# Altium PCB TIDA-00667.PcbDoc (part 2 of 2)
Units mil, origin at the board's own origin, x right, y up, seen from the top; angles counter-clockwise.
Board outline 4000 x 4000 mil, 6 copper layers (Top, Inner Layer 2, Inner Layer 3, Inner Layer 4, Inner Layer 5, Bottom), stack 58.1 mil thick; 114 components, 88 nets, 384 pads, 631 vias.
Unrouted connection lines stored in the file: 538.
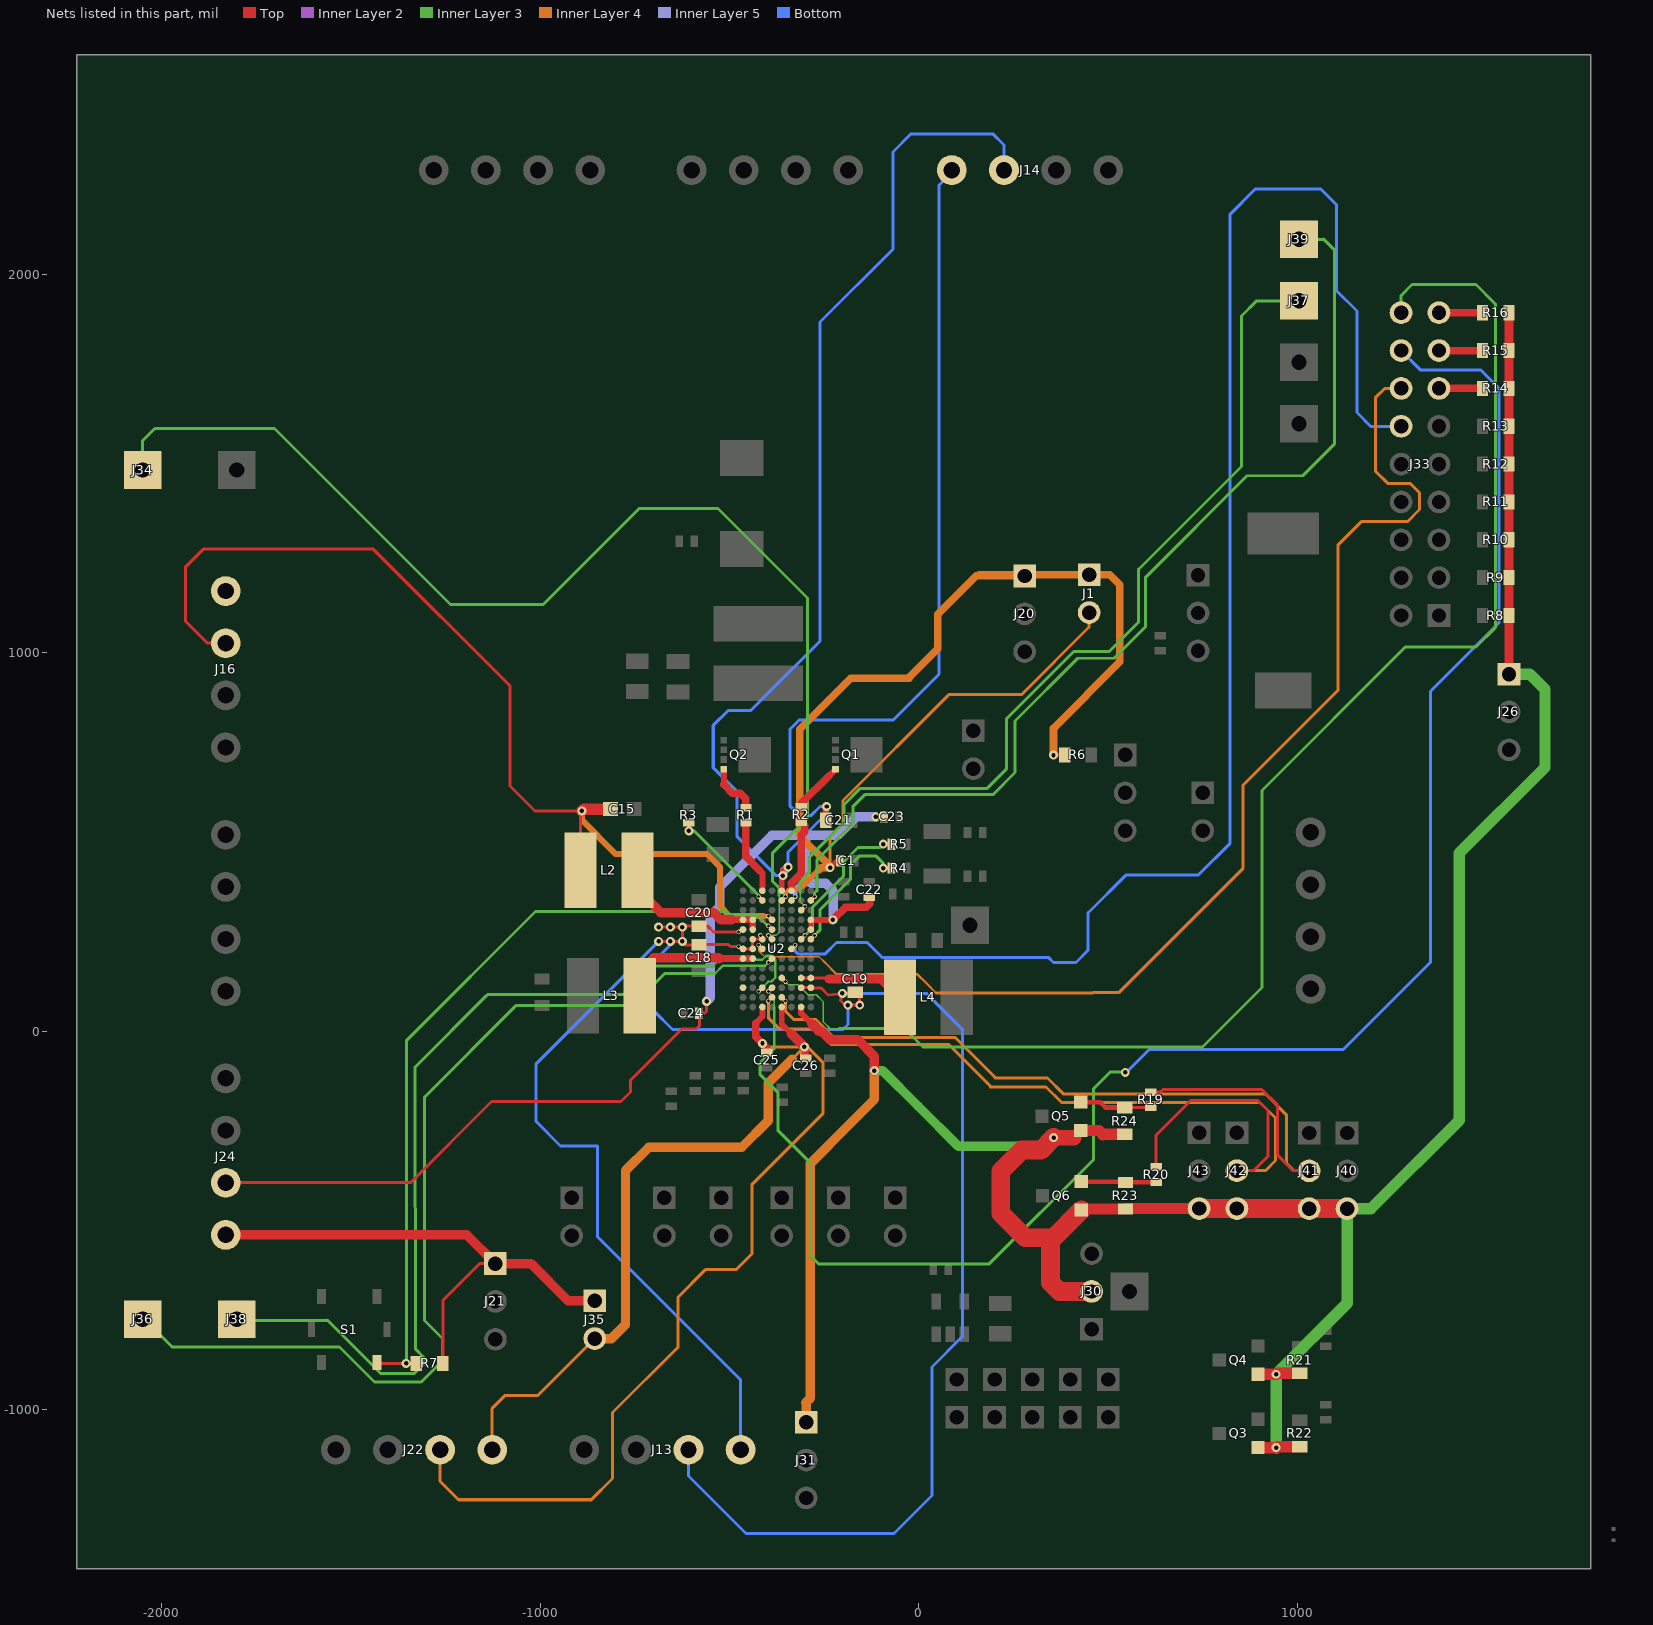
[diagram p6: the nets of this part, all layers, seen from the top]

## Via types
v1: diameter 23.62/23.62/23.62/23.62/23.62/23.62 (per signal layer), hole 11.81, Top to Bottom, 568 vias
v2: diameter 11.81/11.81/11.81/11.81/11.81/11.81 (per signal layer), hole 7.87, Top to Bottom, 63 vias

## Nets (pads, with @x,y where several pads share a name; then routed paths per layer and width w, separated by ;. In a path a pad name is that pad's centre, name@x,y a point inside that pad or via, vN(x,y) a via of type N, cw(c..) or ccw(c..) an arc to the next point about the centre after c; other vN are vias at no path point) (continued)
NetJ33_12: J33.12 U2.G6 | length 4095.4
  Top w9.84: U2.G6@-336.61,217.5 v2(-326.72,227.39)
  Bottom w7.87: v2(-326.72,227.39) -326.72,211.39 -319.91,204.58 -247.12,204.58 -217.42,234.28 -136.48,234.28 -97.47,195.27 342.14,195.27 355.67,181.74 415.01,181.74 447,213.73 447,313.4 448.37,313.4 548.14,413.17 738.65,413.17 822.35,496.87 822.35,2158.68 888.3,2224.63 1062.47,2224.63 1103.59,2183.51 1103.59,1956.1 1157.23,1902.46 1157.23,1634.4 1193.43,1598.2 1273.9,1598.2 J33.12@1274,1598.3
NetJ33_13: J33.13 R14.2 | length 115
  Top w19.68: J33.13@1374,1698.3 R14.2@1489,1698.3
NetJ33_14: J33.14 U2.G3 | length 3160.3
  Top w9.84: v2(-423.28,227.39) U2.G3@-413.39,217.5
  Inner Layer 4 w4: v2(-423.28,227.39) -423.28,212.87 -407.63,197.22 -263.6,197.22 -248.92,182.54 -248.92,182.29
  Inner Layer 4 w6: -248.92,182.29 -218.12,151.49 -4.67,151.49 21.92,124.9 44.7,101.51
  Inner Layer 4 w7.87: 44.7,101.51 459.73,101.51 460.07,101.85 527.93,101.85 856.8,430.72 856.8,650.52 1107.76,901.48 1107.76,1285.25 1168.74,1346.23 1290.94,1346.23 1322.75,1378.04 1322.75,1422.42 1297.77,1447.4 1238.65,1447.4 1205.73,1480.32 1205.73,1673.3 1230.73,1698.3 J33.14@1274,1698.3
NetJ33_15: J33.15 R15.2 | length 115
  Top w20: J33.15@1374,1798.3 R15.2@1489,1798.3
NetJ33_16: J33.16 U2.L4 | length 4771.2
  Top w9.84: v2(-397.69,105.25) U2.L4@-387.8,115.14
  Inner Layer 3 w4: v2(-397.69,105.25) -382.06,89.62 -382.06,61.83
  Inner Layer 3 w7.87: -382.06,61.83 -382.06,-45.75 -420.29,-83.98 -420.29,-113.45 -372.73,-161.01 -372.73,-263.9 -370.42,-263.9 -285.82,-348.5 -285.82,-593.99 -265.38,-614.43 185.95,-614.43 461.81,-338.57 461.81,-151.44 504.95,-108.3 544.99,-108.3 v1(545.18,-108.48)
  Bottom w7.87: v1(545.18,-108.48) 548.38,-108.48 609.15,-47.71 1121.88,-47.71 1351.68,182.09 1351.68,864.22 1351.68,897.91 1532.94,1079.17 1532.94,1698.63 1484.66,1746.91 1323.51,1746.91 1323.51,1748.79 J33.16@1274,1798.3
NetJ33_17: J33.17 R16.2 | length 115
  Top w19.68: J33.17@1374,1898.3 R16.2@1489,1898.3
NetJ33_18: J33.18 U2.K5 | length 3939.4
  Top w9.84: U2.K5@-362.2,140.73 v2(-352.31,130.84)
  Inner Layer 3 w4: v2(-352.31,130.84) -343.67,122.24 -318.63,122.24 -292.83,96.44 -271.19,96.44 -252.3,77.55 -252.3,24.3 -234.34,6.34 -211.31,6.34 -210.86,6.79
  Inner Layer 3 w7.87: -210.86,6.79 -37.61,6.79 10.85,-41.67 749.29,-41.67 906.36,115.4 906.36,636.19 1285.25,1015.08 1471.98,1015.08 1523,1066.1 1523,1921.48 1471.92,1972.56 1303.09,1972.56 1273.57,1943.04 1274,1942.61 J33.18@1274,1898.3
NetJ34_1: J34.1 U2.F4 | length 3218.4
  Top w9.84: v2(-397.69,252.98) U2.F4@-387.8,243.09
  Inner Layer 3 w4: v2(-397.69,252.98) -377.08,252.98 -368.98,261.08 -368.98,359.15
  Inner Layer 3 w7.87: J34.1@-2050.51,1482.46 J34.1@-2050.51,1482.46 -2050.47,1560.46 -2018.39,1592.54 -1702.27,1592.54 -1237.14,1127.41 -992.27,1127.41 -739.08,1380.6 -739.08,1380.7 -530.39,1380.7 -294.51,1144.82 -294.51,562.65 -387.22,469.94 -387.22,396.79 -368.98,378.55 -368.98,359.15
NetJ36_1: J36.1 U2.H4 | length 2670.5
  Top w9.84: v2(-397.69,182.02) U2.H4@-387.8,191.91
  Inner Layer 3 w6: -538.23,152.88 -518.75,172.36 -518.75,172.75 -405.73,172.75 -397.69,180.79 v2@-397.69,181.13
  Inner Layer 3 w7.87: J36.1@-2050.51,-761.03 -2045.6,-761.03 -1972.7,-833.93 -1530.43,-833.93 -1437.96,-926.4 -1314.72,-926.4 -1258.75,-870.43 -1258.75,-811.67 -1306.32,-764.1 -1306.32,-174.26 -1063.43,68.63 -754.79,68.63 -670.54,152.88 -538.23,152.88 ; v2@-397.69,181.13 v2(-397.69,182.02)
NetJ37_1: J37.1 U2.C7 | length 2482.7
  Top w9.84: U2.C7@-311.02,319.86 v2(-301.13,329.75)
  Inner Layer 3 w4: -313.89,369.6 -313.89,342.65 v2(-301.13,329.75)
  Inner Layer 3 w7.87: 852.59,1492 852.59,1889.84 892.34,1929.59 1003.61,1929.59 J37.1@1003.8,1929.78
  Inner Layer 3 w8: -313.89,369.6 -314.03,394.95 -289.44,419.54 -289.44,459.3 -197.28,551.46 -197.28,599.09 -154.5,641.87 180.56,641.87 231.05,692.36 231.05,824.97 409.27,1003.19 503.16,1003.19 579.79,1079.82 579.79,1221.1 581.69,1221.1 852.59,1492
NetJ38_1: J38.1 U2.L3 | length 2562.1
  Top w9.84: v2(-423.28,105.25) U2.L3@-413.39,115.14
  Inner Layer 3 w6: J38.1@-1803.6,-764.27 J38.1@-1795.72,-764.27 ; -543.24,172.83 -527.53,188.54 -527.53,188.91 -413.58,188.91 -402.95,199.54 -389.1,199.54 -379.39,189.83 -379.39,141.33 -389.1,131.62 -397.88,131.62 -397.88,130.64 v2(-423.28,105.25)
  Inner Layer 3 w8: J38.1@-1803.6,-764.27 J38.1@-1802.04,-761.03 ; J38.1@-1795.72,-764.27 -1564.87,-764.27 -1563.24,-762.64 -1422.02,-903.86 -1332.6,-903.86 -1307.62,-878.88 -1307.62,-861.86 -1330.33,-839.15 -1330.63,-94.34 -1144.1,92.19 -1139.78,96.5 -779.49,96.5 -703.16,172.83 -543.24,172.83
NetJ39_1: J39.1 U2.B8 | length 2737.5
  Top w9.84: U2.B8@-285.43,345.45 v2(-275.54,355.34)
  Inner Layer 3 w7.87: v2(-275.54,355.34) -275.54,365.3 -269.7,371.14 -269.7,452.35 -174.49,547.56 -174.49,593.27 -142.75,625.01 195.94,625.01 254.22,683.29 254.22,819.62 419.97,985.37 515.36,985.37 599.12,1069.13 599.12,1199.53 867.09,1467.5 1014.1,1467.5 1097.57,1550.97 1097.57,2064.26 1069.47,2092.36 1069.39,2092.28 J39.1@1003.8,2092.28
NetL2_1: L2.1 U2.D1 U2.D2 U2.E2 | length 499.9
  Top w3.94: U2.E2@-438.98,268.68 U2.E2@-438.98,270.94
  Top w7.87: L2.1@-743.75,425 L2.1@-740,468.75
  Top w17: -493.75,294.27 U2.D1@-464.57,294.27 U2.D2@-438.98,294.27 U2.E2@-438.98,270.94
  Top w25: L2.1@-740,468.75 -740,371.27 -682,313.27 -542,313.27 -523,294.27 -493.75,294.27
NetL3_1: L3.1 U2.H1 U2.H2 | length 490.4
  Top w7.87: L3.1@-741.91,39.41 L3.1@-737.5,93.75 ; -700,194 -699.91,194
  Top w12: U2.H1@-464.57,191.91 -464.57,192 U2.H1@-464.57,194
  Top w18: -527,192 U2.H1@-464.57,192 ; U2.H1@-464.57,191.91 U2.H2@-438.98,191.91
  Top w25: L3.1@-741.91,39.41 -741.91,152.09 -700,194 ; -699.91,194 -529,194 -527,192
NetL4_1: L4.1 U2.K7 U2.K8 | length 287.4
  Top w7.87: U2.K7@-311.02,140.73 U2.K8@-285.43,140.73 -239.73,140.73 -238.36,139.36 ; -237,138 -238.36,139.36 ; -235,135.12 -238.36,138.48 -238.36,139.36
  Top w25: -237,138 -99,138 L4.1@-50,90
NetQ1_4: Q1.4 R2.2 | length 137.1
  Top w16: -236.87,675.37 Q1.4@-220.12,692.12
  Top w20: R2.2@-310.31,592.4 -310.31,601.93 -236.87,675.37
NetQ2_4: Q2.4 R1.2 | length 137.7
  Top w16: -515.28,651.87 Q2.4@-515.28,692.12
  Top w20: -515.28,651.87 -492.49,629.08 -472.18,629.08 -456.78,613.68 R1.2@-456.78,590.58
NetR1_1: R1.1 U2.A3 | length 198.5
  Top w10: R1.1@-457.91,549.45 R1.1@-456.78,550.58
  Top w16: -419.82,424.38 -413.39,417.95 U2.A3@-413.39,371.04
  Top w20: R1.1@-457.91,549.45 -457.91,462.35 -457.79,462.35 -419.82,424.38
NetR2_1: R2.1 U2.A6 | length 199.5
  Top w10: R2.1@-301.51,542.56 R2.1@-301.51,543.6
  Top w17: U2.A6@-336.61,371.04 -336.61,390.77
  Top w20: -336.61,390.77 -310.31,417.07 -310.31,517.92 -301.51,526.72 R2.1@-301.51,542.56 ; R2.1@-310.31,552.4 R2.1@-301.51,543.6
NetR3_1: R3.1 U2.B3 | length 294.4
  Top w7.87: v1(-607.76,529.24) R3.1@-607.76,550.58
  Top w9.84: v2(-423.28,355.34) U2.B3@-413.39,345.45
  Inner Layer 3 w7.87: v1(-607.76,529.24) -594.83,529.24 -594.25,529.82 -465.41,400.97 -423.28,358.84 v2(-423.28,355.34)
NetR4_2: R4.2 U2.F8 | length 378.3
  Top w7.87: v1(-94.09,431.13) -94.09,431.21 R4.2@-72.2,431.21
  Top w9.84: U2.F8@-285.43,243.09 v2(-275.54,252.98)
  Inner Layer 3 w7.87: v2(-275.54,252.98) -261.72,266.8 -261.72,320.23 -180.67,401.28 -180.67,439.51 -157.64,462.54 -112.89,462.54 -94.09,443.74 -94.09,443.66 v1(-94.09,431.13)
NetR5_2: R5.2 U2.F7 | length 397.5
  Top w7.87: v1(-94.09,494.12) -93.68,493.71 R5.2@-72.2,493.71
  Top w9.84: U2.F7@-311.02,243.09 v2(-301.13,252.98)
  Inner Layer 3 w6: v2(-301.13,252.98) -280.99,273.12
  Inner Layer 3 w8: -280.99,273.12 -280.99,327.6 -199.01,409.58 -199.01,447.34 -160.78,485.57 -101.84,485.57 -94.09,493.32 v1(-94.09,494.12)
NetR7_2: R7.2 S1.B U2.E4 | length 2086.7
  Top w7.87: S1.B@-1431.97,-875.13 -1429.52,-875.13 -1427.41,-877.23 v1(-1354.58,-877.23) -1354.58,-877.63 R7.2@-1327.47,-877.63
  Top w9.84: v2(-397.69,278.57) U2.E4@-387.8,268.68
  Inner Layer 3 w7.87: v1(-1354.58,-877.23) -1353.42,-876.08 -1353.42,-23.54 -1352.71,-23.54 -1012.52,316.65 -507.64,316.65 -496.2,305.21 -426.11,305.21 -400.05,279.15 -400.05,278.57 v2(-397.69,278.57)
SCL_S: Q6.2 R20.2 R23.1 | length 199.1
  Top w12: Q6.2@429.18,-397.26 542.93,-397.26 R23.1@545.43,-399.76 546.68,-398.51 R20.2@626.68,-398.51
SCL_SCK: J42.2 R20.1 U2.M4 | length 2381.4
  Top w8: R20.1@626.68,-358.51 626.68,-275.04 626.34,-274.7 717.56,-183.48 896.03,-183.48 922.14,-209.59 922.14,-330.48 884.68,-367.94 840.65,-367.94 J42.2@840.27,-368.32
  Top w10: v2(-397.69,79.66) U2.M4@-387.8,89.55
  Inner Layer 4 w7.87: v2(-397.69,79.66) -397.64,35.61 -367.43,5.4 -273.19,5.47 -232.42,-35.31 -232.22,-35.11 78.94,-35.11 188.6,-144.77 188.6,-147.12 335.85,-147.12 377.2,-188.47 901.21,-188.47 942.2,-229.46 942.2,-341.75 915.47,-368.48 915.31,-368.32 J42.2@840.27,-368.32
SDA_S: Q5.2 R19.2 R24.1 | length 191.2
  Top w8: R24.1@543.99,-202.13 R19.2@612.74,-200.88
  Top w12: Q5.2@427.74,-187.13 478.63,-187.13 492.94,-201.44 543.3,-201.44 R24.1@543.99,-202.13
SDA_SDI: J41.2 R19.1 U2.M5 | length 2267.2
  Top w7.87: U2.M5@-362.2,89.55 -352.31,77.34 v2(-352.31,79.66)
  Top w8: R19.1@612.74,-160.88 637.79,-160.88 637.84,-160.93 644.99,-153.78 905.78,-153.78 947.76,-195.76 947.76,-327.37 988.61,-368.22 1030.72,-368.22 J41.2@1031.25,-368.75
  Inner Layer 4 w7.87: v2(-352.31,79.66) -352.31,52.68 -330.68,31.05 -271.54,31.05 -222.83,-17.66 -222.28,-17.1 96.48,-17.1 201.66,-122.28 201.66,-123.78 340.03,-123.78 381.55,-165.3 915.47,-165.3 970.72,-220.55 970.72,-348.87 990.32,-368.47 J41.2@1031.25,-368.75
VBAT_DCDC: C18.2 C19.2 C20.2 J13.3 J13.4 U2.E1 U2.F2 U2.F3 U2.G1 U2.G2 U2.L7 U2.L8 | length 5825
  Top w7.87: v1(-687.5,237.5) v1(-656.25,237.5) v1(-625,237.5) ; v1(-687.5,275) v1(-656.25,275) v1(-625,275) ; U2.G1@-464.57,217.5 U2.G1@-462.28,217.5 ; U2.E1@-464.57,268.68 v2(-476.14,262.5) -542.6,262.5 -557.6,277.5 C20.2@-581.25,277.5 -627,277.5 -625,275.5 v1(-625,275) ; v2(-418.75,252.98) -418.75,250.03 -413.39,244.67 U2.F3@-413.39,243.09 U2.F2@-438.98,243.09 U2.G2@-438.98,217.5 U2.G1@-462.28,217.5 ; U2.L7@-311.02,115.14 U2.L8@-285.43,115.14 -284.3,114 -258,114 -240,96 v1(-201.93,100.24) -207,81 -195,69 -187.75,69 v1(-187.5,68.75) v1(-156.25,68.75) -156.25,99 -162.25,105 -166,105 C19.2@-168,103 ; v1(-625,237.5) v1(-625,275) ; v1(-625,237.5) -615,227.5 -582.5,227.5 C18.2@-581.25,228.75 -502.67,228.75 -498.03,224.11 -498.03,223.33 -490.54,223.33 -490.39,223.48 v2(-476.14,223.48) -469.53,217.58 U2.G1@-462.28,217.5
  Bottom w7.87: v1(-687.5,237.5) -1010.93,-85.93 -1010.93,-238.56 -946.58,-302.91 -848.64,-302.91 -848.64,-543.56 -470.85,-921.35 J13.4@-470.85,-1105.57 ; v1(-656.25,237.5) -656.25,228.75 -702,183 -702,55.5 -651,4.5 -201,4.5 -187.5,18 v1(-187.5,68.75) ; J13.3@-608.64,-1105.57 -608.64,-1175 -456.52,-1327.12 -65.9,-1327.12 34.83,-1226.39 34.83,-886.74 114.89,-806.68 114.89,4.9 19.55,100.24 v1(-201.93,100.24)
VBAT_DCDCCTRL: C21.2 J14.3 J14.4 U2.A5 | length 5117.7
  Top w7.87: v1@-246.46,595.4 -245.4,595.4 v1(-243.75,593.75)
  Top w15: C21.2@-246.46,557.28 v1@-246.46,595.4
  Top w15.75: U2.A5@-362.2,371.04 -362.2,408.17 v1(-359.11,411.26)
  Top w16: v1(-359.11,411.26) -359.15,423.24 -349,433.51 v1(-345.37,433.67)
  Inner Layer 2 w7.87: v1@-350.87,433.83 v1@-345.53,433.83
  Inner Layer 2 w16: v1(-359.11,411.26) -359.11,425.59 v1@-350.87,433.83 ; v1@-345.53,433.83 v1(-345.37,433.67)
  Inner Layer 5 w7.87: v1(-359.11,411.26) v1@-359.01,411.42
  Inner Layer 5 w16: v1@-359.01,411.42 v1(-345.37,433.67)
  Bottom w7.87: v1(-345.37,433.67) -345.37,473.7 -242.45,576.62 -242.45,592.45 v1(-243.75,593.75) -261.15,593.75 -285.56,569.34 -315.8,569.34 -315.8,570.35 -340.86,595.41 -340.86,797.48 -316.71,821.63 -68.22,821.63 53.32,943.17 53.32,2235.01 87.06,2268.75 J14.4@87.06,2275
  Bottom w8: v1(-359.11,411.26) -359.48,410.89 -377.12,410.89 -480.06,513.83 -480.06,632.94 -543.17,696.05 -543.17,808.18 -503.9,847.45 -444.1,847.45 -261.06,1030.49 -261.06,1873.71 -68.57,2066.2 -68.57,2323.04 -20.86,2370.75 195.39,2370.75 224.98,2341.16 224.98,2275.13 J14.3@224.85,2275
VBAT_LDO: J21.1 R7.1
VBAT_LDO_F: C22.1 C23.1 C24.1 J24.3 J24.4 J35.1 U2.B6 U2.D8 U2.E8 U2.L1 | length 4313.8
  Top w7.87: J24.3@-1831.25,-400.15 -1343.34,-400.15 -1128.85,-185.66 -787.09,-185.66 -762.11,-160.68 ; -1257.47,-877.63 -1257.47,-711 -1160.22,-613.75 -1118.75,-613.75 ; C24.1@-581.46,47.84 -581.07,48.23 -565.32,48.23 -560.88,52.67 v1(-560.88,78.9)
  Top w8: -762.11,-160.68 -762.11,-130.29 -626.07,5.75 -588.61,5.75 -579.21,15.15 -579.21,44.07 -579.21,45.59 C24.1@-581.46,47.84
  Top w9.84: U2.B6@-336.61,345.45 v2(-326.72,355.34)
  Top w11.81: U2.E8@-285.43,268.68 U2.D8@-285.43,294.27
  Top w15.75: U2.D8@-285.43,294.27 -226.97,294.27 v1(-226.97,294.57)
  Top w19.68: v1(-113.78,566.47) C23.1@-92.19,566.47
  Top w20: v1(-226.97,294.57) -193.81,327.73 -138.95,327.73 -130.15,336.53 -130.15,353.13 C22.1@-131.27,354.25
  Top w25: J24.4@-1831.25,-537.94 -1194.56,-537.94 -1118.75,-613.75 -1025,-613.75 -926.75,-712 J35.1@-856.25,-712
  Inner Layer 5 w12: v2(-326.72,355.34) -326.72,378.5 -325.96,378.5 -299.17,405.29
  Inner Layer 5 w25: v1(-560.88,78.9) -551.58,88.2 -551.58,305.99 -549.67,305.99 -526.04,329.62 -526.04,380.27 -388.76,517.55 -299.17,517.55 ; v1(-226.97,294.57) -225.75,295.79 -225.75,370.26 -246.21,390.72 -284.6,390.72 -299.17,405.29 -299.17,517.55 ; v1(-113.78,566.47) -114.08,566.17 -165.54,566.17 -214.16,517.55 -299.17,517.55
VBAT_VCC3_VCC6: C25.1 C26.1 J22.3 J22.4 J35.2 U2.N3 U2.N5 | length 4114.7
  Top w15.75: U2.N5@-362.2,63.96 -362.2,18.39 -337.7,-6.12
  Top w16: -431.01,21.25 -413.34,38.92 -413.34,63.91 U2.N3@-413.39,63.96
  Top w18: v1(-302.51,-41.31) -299.14,-44.68 C26.1@-299.14,-71.12
  Top w20: -431.01,21.25 -431.01,-14.34 v1(-413.12,-32.23) -401.93,-43.42 C25.1@-401.93,-56.23
  Top w25: -337.7,-6.12 v1(-302.51,-41.31)
  Inner Layer 4 w7.87: J22.4@-1127.1,-1105.57 -1127.1,-996.13 -1092.8,-961.83 -1006.08,-961.83 J35.2@-856.25,-812 ; v1(-413.12,-32.23) -409.5,-32.23 -400.42,-41.31 v1(-302.51,-41.31) -310.35,-49.15 -310.35,-82.57 ; -334.5,-73.3 v1@-304.6,-43.4
  Inner Layer 4 w8: J22.3@-1264.89,-1105.57 -1265.29,-1105.97 -1265.29,-1188.64 -1216.24,-1237.69 -865.41,-1237.69 -809.45,-1181.73 -809.45,-1007.45 -636,-834 -636,-702 -564,-630 -483,-630 -440.38,-587.38 -440.38,-404.23 -288.49,-252.34 -252.7,-216.55 -252.7,-83.14 -293.91,-41.93 -303.13,-41.93 v1@-304.6,-43.4
  Inner Layer 4 w25: J35.2@-856.25,-812 -812,-812 -775,-775 -775,-368.25 -713.37,-306.63 -468.1,-306.63 -398.47,-237 -398.47,-137.27 -334.5,-73.3 ; v1@-304.6,-43.4 v1(-302.51,-41.31)
VCCPINT_1V0: C15.2 J16.1 J16.2 L2.2 U2.D4 | length 2709.9
  Top w7.87: L2.2@-893.75,425 -893.75,578.57 v1(-890.35,581.97)
  Top w8: J16.2@-1831.25,1025.15 -1831.51,1025.41 -1879.8,1025.41 -1936.83,1082.44 -1936.83,1227.25 -1890.49,1273.59 -1441.36,1273.59 -1080.26,912.49 -1080.26,647.91 -1014.32,581.97 v1(-890.35,581.97)
  Top w9.84: v2(-397.69,304.16) U2.D4@-387.8,294.27
  Top w30: v1(-890.35,581.97) -885.57,586.75 C15.2@-818.62,586.75
  Inner Layer 4 w12: -410.44,304.12 -410.4,304.16 v2(-397.69,304.16)
  Inner Layer 4 w16: v1(-890.35,581.97) -890.35,559.1 -801.98,468.56 -559.81,468.56 -525,433.75 -525,330 -499.12,304.12 -410.44,304.12
VDDIO: J26.1 J30.2 J31.1 J40.3 J41.3 J42.3 J43.3 Q3.1 Q4.1 Q5.1 Q6.1 R8.1 R9.1 R10.1 R11.1 R12.1 R13.1 R14.1 R15.1 R16.1 R21.2 R22.2 R23.2 R24.2 U2.N7 | length 7193.6
  Top w15.75: U2.N7@-311.02,63.96 -311.02,47.18 -283.32,19.47
  Top w25: -283.32,19.47 -264.07,0.23 -257.68,0.23 -235.33,-22.12 -192,-22.12 -161.6,-22.12 -117.35,-66.37 v1(-117.35,-103.79) ; R8.1@1559,1098.3 R9.1@1559,1198.3 R10.1@1559,1298.3 R11.1@1559,1398.3 R12.1@1559,1498.3 R13.1@1559,1598.3 R14.1@1559,1698.3 R15.1@1559,1798.3 R16.1@1559,1898.3 ; J26.1@1559.03,943.44 R8.1@1559,1098.3
  Top w30: 409.57,-280.3 Q5.1@427.74,-262.13 475.37,-262.13 486.25,-273.01 487.13,-272.13 R24.2@543.99,-272.13 ; Q6.1@429.18,-472.26 431.68,-469.76 R23.2@545.43,-469.76 546.87,-468.32 J43.3@740.27,-468.32 ; Q3.1@896.25,-1100 v1@945.12,-1100 ; Q4.1@896.25,-906.25 v1(943.75,-906.25) 946.25,-903.75 R21.2@1006.25,-903.75 ; v1(943.75,-1100) v1@945.12,-1100 ; R22.2@1006.25,-1097.5 947.62,-1097.5 v1@945.12,-1100
  Top w40: v1(356.25,-281.25) 409.57,-281.25 409.57,-280.3
  Top w50: v1(356.25,-281.25) 355.52,-281.25 322.88,-313.89 271.86,-313.89 216.24,-369.51 216.24,-480.76 280.99,-545.51 350.86,-545.51 353.4,-548.04 ; Q6.1@429.18,-472.26 353.4,-548.04 ; J30.2@456.25,-687.5 371.11,-687.5 347.25,-663.64 347.25,-554.19 353.4,-548.04 ; J43.3@740.27,-468.32 J42.3@840.27,-468.32 1030.82,-468.32 J41.3@1031.25,-468.75 J40.3@1131.25,-468.75
  Inner Layer 3 w25: v1(-117.35,-103.79) -96.19,-103.79 -96.1,-103.7 -1.79,-198.01 103.74,-303.54 333.96,-303.54 v1(356.25,-281.25)
  Inner Layer 3 w30: v1(943.75,-1100) v1(943.75,-906.25) 1131.62,-718.38 1131.62,-469.12 J40.3@1131.25,-468.75 1192.53,-468.75 1193.41,-469.63 1427.65,-235.38 1427.65,469.76 1427.34,470.07 1653.99,696.72 1653.99,903.45 1614,943.44 J26.1@1559.03,943.44
  Inner Layer 4 w25: J31.1@-297.57,-1032.96 -297.57,-983.51 -299.4,-981.68 -286.68,-968.96 -286.68,-349.03 -181.4,-243.75 -117.31,-179.66 -117.31,-103.83 v1(-117.35,-103.79)
VRTC: J20.1 R6.1
VRTC_F: C1.1 J1.1 J1.2 U2.B5 | length 3435.6
  Top w7.87: v1(355.71,729.61) 355.71,730 385,730
  Top w9.84: U2.B5@-362.2,345.45 v2(-352.31,355.34)
  Top w12: v1(-234.63,432.28) -216.51,450.4 -209.61,450.4 C1.1@-209.39,450.18
  Inner Layer 4 w7.87: v1(-234.63,432.28) -234.63,433.5 -234.63,515.28 -200.62,549.29 -200.62,609.9 78.76,889.28 271.29,889.28 448.37,1066.36 448.96,1066.36 448.96,1104.96 J1.2@450,1106
  Inner Layer 4 w12: v2(-352.31,355.34) -352.31,364.77 -340.85,376.23 -314.35,376.23 -306.22,384.36
  Inner Layer 4 w16: -306.22,384.36 -263.23,427.35
  Inner Layer 4 w20: -263.23,427.35 -258.46,432.12 -253.54,432.12 v1(-234.63,432.28) ; v1@-234.63,433.5 -234.63,435.45 -314.38,515.2 -314.38,797.2 -179.41,932.17 -81.86,932.17 -81.73,932.04 -81.01,932.76 -25.56,932.76 -25.56,935.38 49.69,1010.62 49.69,1101 151.48,1202.8 156.36,1202.8 ; v1(355.71,729.61) 355.71,801 531,976.29 531,1179 504,1206 J1.1@450,1206 289.44,1206 ; 156.36,1202.8 279.4,1202.8 282.6,1206 289.44,1206 ; 156.36,1202.8 159.56,1206 289.44,1206
pads on no net: J29.3 J29.4 J29.7 J29.8 S1.A' S1.B' S1.M1 S1.M2 U1.4

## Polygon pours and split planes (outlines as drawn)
AGND on Inner Layer 5 "Inner Layer 5-AGND" (solid, remove dead copper, shelved, pour order 2): -2181.25,2537.5 1731.25,2537.5 1731.25,-1368.75 -2181.25,-1368.75
AGND on Top "Top-AGND" (solid, remove dead copper, shelved, pour order 4): -2301.77,2642.5 1872.69,2642.5 1872.69,-1528.76 -2301.77,-1528.76
AGND on Inner Layer 3 "Inner Layer 3-AGND" (solid, remove dead copper, shelved, pour order 6): -2318.75,2656.25 1856.25,2656.25 1856.25,-1500 -2318.75,-1500
AGND on Bottom "Bottom-AGND" (solid, remove dead copper, shelved, pour order 8): -2285.78,2632.9 1850.3,2632.9 1850.3,-1471.18 -2285.78,-1471.18
AGND on Inner Layer 2 "Inner Layer 2-AGND" (solid, remove dead copper, shelved, pour order 10): 1757.19,2562.19 -2207.19,2562.19 -2207.19,-1402.19 1757.19,-1402.19
AGND on Inner Layer 4 "Inner Layer 4-AGND" (solid, remove dead copper, shelved, pour order 12): -2268.75,2618.75 1850,2618.75 1850,-1475 -2268.75,-1475

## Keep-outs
Keep-Out Layer:
  region: -900,206.25 -875,206.25 -875,193.75 -843.75,193.75 -843.75,-87.5 -931.25,-87.5 -931.25,-12.5 -1212.5,-12.5 -1275,50 -1493.75,50 -1737.5,293.75 -1737.5,393.75 -1793.75,450 -1881.25,450 -1912.5,481.25 -1912.5,600 -1856.25,656.25 -1681.25,656.25 -1125,100 -931.25,100 -931.25,193.75 -900,193.75 -900,206.25
  pour cut-out: -1023.8,117.92 -1023.8,191.54 -1009.97,205.37 -981.76,205.37 -967.46,191.07 -967.46,117.92 -1023.8,117.92
  pour cut-out: -1884.47,787.26 -1884.47,719.29 -1830.6,665.42 -1773.84,665.42 -1596.51,485.87 -770.96,485.87 -688.99,569.71 -689.17,600.54 -703.81,615.18 -734.78,614.52 -812.88,529.38 -1554.75,529.38 -1748.91,731.94 -1748.91,786.53 -1769.33,806.95 -1872.9,806.95 -1884.19,795.66 -1884.19,787.26 -1884.47,787.26
  region: 6970,4770 7070,4770 7070,4870 6970,4870 6970,4770
  region: 8220.47,4769.68 8320.47,4769.68 8320.47,4869.68 8220.47,4869.68 8220.47,4769.68
  region: -304.4,227.86 -305.28,230.58 -301.2,236.17 -247.05,236.17 92.76,575.98 257.13,575.98 257.13,474.05 386.85,474.05 386.85,449.08 257.13,449.08 257.13,373.02 33.5,373.02 6.25,400.27 -23.26,400.27 -109.54,313.99 -109.54,254.96 -132.81,231.69 -192.55,231.69 -211.48,211.36 -299.96,211.36 -304.4,215.8 -304.4,227.86
  region: -287.42,326.92 -283.59,330.75 -276.89,330.75 -241.15,366.49 -169.87,366.49 -169.87,354.61 -179.68,344.8 -207.05,344.8 -241.63,310.22 -284.82,310.22 -287.43,312.83 -287.43,326.92 -287.42,326.92
  region: -543.34,1027.39 -543.34,1133.86 -554.12,1144.64 -554.12,1260.08 -573.39,1279.35 -602.88,1279.35 -602.88,1309.47 -548.71,1309.47 -508.64,1349.54 -443.45,1349.54 -365.65,1427.34 -365.65,2092.42 -255.65,2202.42 -255.65,2299.38 -223.05,2331.98 -133.15,2331.98 -49.62,2248.45 -49.62,1119.16 -141.39,1027.39 -543.34,1027.39
  pour cut-out: 983.97,559.87 983.97,498.07 1009.29,472.75 1067.28,472.75 1088.46,494.04 1088.11,558.5 1068.81,577.74 1001.96,577.87 983.97,559.87
  pour cut-out: -479.75,338.26 -479.75,149.44 -430.93,149.44 -430.93,127.33 -274.35,127.33 -274.35,201.02 -321.78,201.02 -321.78,149.44 -371.52,149.44 -371.52,205.62 -354.71,222.43 -303.82,222.43 -303.82,345.63 -393.63,345.63 -393.63,283.45 -418.96,283.45 -418.96,328.13 -429.09,338.26 -479.75,338.26
  pour cut-out: 976.65,567.08 976.65,495.5 1001.6,470.55 1064.86,470.55 1094.33,500.02 1094.33,567.8 1066.57,595.56 996.14,595.56 976.57,575.99 976.57,567.08 976.65,567.08
  pour cut-out: -1888.35,782.14 -1888.35,710.56 -1863.4,685.61 -1800.14,685.61 -1770.67,715.08 -1770.67,782.86 -1798.43,810.62 -1868.86,810.62 -1888.43,791.05 -1888.43,782.14 -1888.35,782.14
  pour cut-out: -1884.3,144.66 -1884.3,66.37 -1866.56,48.63 -1794.49,48.63 -1773.18,69.94 -1773.18,142.59 -1792.49,161.9 -1869.74,161.9 -1884.19,147.45 -1884.19,144.66 -1884.3,144.66
  pour cut-out: -1885.19,140.74 -1885.19,78.94 -1859.87,53.62 -1801.88,53.62 -1780.7,74.92 -1781.05,139.37 -1800.35,158.61 -1867.2,158.74 -1885.19,140.74
  region: -543.27,968.5 -209.81,968.5 -95.8,854.49 -95.8,683.2 -180.86,683.2 -180.86,778.96 -204.37,802.47 -275.57,802.47 -294.07,783.97 -294.07,676.47 -354.22,616.32 -354.22,486.42 -379.38,461.26 -379.38,371.28 -396.49,371.28 -396.49,460.99 -427.22,491.72 -427.22,634.55 -403.18,658.59 -380.91,658.59 -362.03,677.47 -362.03,782.78 -349.93,794.88 -349.93,814.66 -364.96,829.69 -491.59,829.69 -506.25,815.03 -506.25,709.18 -554.2,709.18 -580.92,735.9 -580.92,804.76 -543.27,842.41 -543.27,968.5
  pour cut-out: -657.13,2315.52 -657.13,2237.23 -639.39,2219.49 -567.32,2219.49 -546.01,2240.8 -546.01,2313.45 -565.32,2332.76 -642.57,2332.76 -657.02,2318.31 -657.02,2315.52 -657.13,2315.52
  region: -315.76,168.28 -315.76,159.56 -311.59,155.39 -265.96,155.39 -258.04,163.31 -258.04,171.61 -314.17,171.61 -315.65,170.13 -315.65,168.28 -315.76,168.28
  region: 4470,4570 4570,4570 4570,4670 4470,4670 4470,4570
  region: -14.37,-42.05 -14.37,-105.04 103.74,-105.04 103.74,-42.05 76.18,-42.05 76.18,-42 15.16,-42 15.16,-42.05 -14.37,-42.05
  pour cut-out: -526.31,1570.96 -526.31,1688.38 -526.24,1688.38 -440.56,1774.06 -440.56,2002.61 -646.71,2208.76 -646.71,2306.83 -627.88,2325.66 -571.61,2325.66 -555.39,2309.44 -555.39,2192.76 -380.89,2018.26 -379.54,1675.73 -394.62,1660.66 -394.62,1575.14 -410.28,1559.82 -515.14,1559.82 -526.31,1570.96
  pour cut-out: -652.83,2309.17 -652.83,2239.36 -633.32,2219.85 -574.51,2219.85 -551.26,2243.1 -551.26,2308.8 -564.68,2322.22 -642,2322.22 -652.88,2311.34 -652.88,2309.17 -652.83,2309.17
  pour cut-out: -1338.64,2308.04 -1338.64,2236.46 -1313.69,2211.51 -1250.43,2211.51 -1220.96,2240.98 -1220.96,2308.76 -1248.72,2336.52 -1319.15,2336.52 -1338.72,2316.95 -1338.72,2308.04 -1338.64,2308.04
  pour cut-out: -1884.3,781.75 -1884.3,712.52 -1863.61,691.83 -1797.76,691.83 -1771.87,717.72 -1771.87,785.27 -1796.84,810.24 -1868.75,810.24 -1884.35,794.64 -1884.35,781.75 -1884.3,781.75
  pour cut-out: -1881.15,142.71 -1881.15,72.9 -1861.64,53.39 -1802.83,53.39 -1779.58,76.64 -1779.58,142.34 -1793,155.76 -1870.32,155.76 -1881.2,144.88 -1881.2,142.71 -1881.15,142.71
  region: -518.28,1594.56 -518.28,1476.2 -412.72,1476.2 -412.72,1594.56 -518.28,1594.56
  region: -545,325 -545,302 -678,302 -703,327 -785,327 -785.13,525 -700.78,525 -700.62,403.28 -622.34,325 -545,325
  region: -631.25,137.5 -600,168.75 -600,175 -562.5,175 -562.5,131.25 -612.5,81.25 -643.75,81.25 -643.75,131.25 -631.25,131.25 -631.25,137.5
  pour cut-out: -1886.85,787.65 -1886.85,709.36 -1869.11,691.62 -1797.04,691.62 -1775.73,712.93 -1775.73,785.58 -1795.04,804.89 -1872.29,804.89 -1886.74,790.44 -1886.74,787.65 -1886.85,787.65
  pour cut-out: -1884.3,273.44 -1884.3,204.21 -1863.61,183.52 -1797.76,183.52 -1771.87,209.41 -1771.87,276.96 -1796.84,301.93 -1868.75,301.93 -1884.35,286.33 -1884.35,273.44 -1884.3,273.44
  pour cut-out: -64.72,256.49 -43.15,256.49 -29.52,242.86 -29.52,175.89 144.74,1.63 420.01,1.63 991.87,573.49 1057.99,573.49 1087.08,544.4 1087.08,501.69 1061.75,476.36 978.53,476.36 451.41,-50.76 112.37,-50.76 -78.89,140.5 -78.89,248.04 -70.35,256.58 -64.72,256.58 -64.72,256.49
  region: 912.8,971.73 1011.22,971.73 1011.22,859.53 912.8,859.53 912.8,971.73
  region: -547,201.06 -547,182.36 -611,182.36 -670.6,122.76 -671.06,21.11 -698.17,-6 -777,-6 -777,191 -720,191 -709.95,201.06 -547,201.06
  pour cut-out: -980.29,204.76 -972.58,212.47 -547.41,212.47 -509.35,174.41 -448.09,174.41 -439.88,166.2 -439.88,149.16 -452.22,136.82 -554.71,136.82 -580.46,162.57 -969.27,162.57 -980.35,173.65 -980.35,204.7 -980.29,204.7 -980.29,204.76
  region: -907,2300 -887,2320 -847,2320 -775,2248 -775,1110 -810,1075 -810,945 -782,917 -609,917 -590,898 -590,835.95 -906.37,835.95 -996,926 -996,2086 -907,2175 -907,2300
  region: -307.96,233.91 -301.74,240.13 -248.83,240.13 91.16,580.12 256.52,580.12 260.82,575.82 260.82,371.73 257.8,368.71 31.44,368.71 3.75,396.4 -22.56,396.4 -105.75,313.21 -105.75,254.13 -130.86,229.02 -191.74,229.02 -212.32,208.44 -300.69,208.44 -307.99,215.74 -307.99,233.88 -307.96,233.88 -307.96,233.91
  pour cut-out: 980.24,559.42 980.24,490.19 1000.93,469.5 1066.78,469.5 1092.67,495.39 1092.67,562.94 1067.7,587.91 995.79,587.91 980.19,572.31 980.19,559.42 980.24,559.42
  region: -220.55,181.6 -220.55,190.96 -195.02,216.49 -141.64,216.49 -134.18,209.03 -134.18,157.87 -216.34,157.87 -220.4,161.93 -220.4,181.6 -220.55,181.6
  region: -232.25,708.62 -207.69,708.62 -203.23,713.08 -203.23,778.32 -210.16,785.25 -269.77,785.25 -279.65,775.37 -279.65,695.75 -271.47,687.57 -254.46,687.57 -244.34,697.69 -244.34,705.21 -240.98,708.57 -232.25,708.57 -232.25,708.62
  pour cut-out: -1332.93,2311.24 -1332.93,2241.43 -1313.42,2221.92 -1254.61,2221.92 -1231.36,2245.17 -1231.36,2310.87 -1244.78,2324.29 -1322.1,2324.29 -1332.98,2313.41 -1332.98,2311.24 -1332.93,2311.24
  pour cut-out: -1336.21,2310.2 -1336.21,2248.4 -1310.89,2223.08 -1252.9,2223.08 -1231.72,2244.38 -1232.07,2308.83 -1251.37,2328.07 -1318.22,2328.2 -1336.21,2310.2
  region: -1881.25,1200 -1881.25,1137.5 -1837.5,1093.75 -1775,1093.75 -1506.25,825 -1350,825 -1312.5,787.5 -1312.5,500 -1231.25,418.75 -937.5,418.75 -937.5,325 -900,325 -900,300 -875,300 -875,325 -850,325 -850,593.75 -931.25,593.75 -931.25,525 -1012.5,525 -1118.75,631.25 -1118.75,893.75 -1462.5,1237.5 -1843.75,1237.5 -1881.25,1200
  region: -1871.6,-626.84 -1871.6,-496.27 -1841.53,-466.2 -1374.96,-466.2 -1113.61,-204.85 -765.28,-204.85 -741.42,-181.37 -741.29,-130.06 -589.53,22.08 -589.53,67.05 -532.57,124.01 -464.05,124.01 -464.05,106.39 -473.93,106.39 -505,75.32 -505,49.62 -681.43,-126.81 -681.43,-275.53 -780.31,-375.28 -971.7,-375.28 -986.59,-390.17 -986.59,-576.05 -959.06,-603.53 -782.38,-603.53 -750.48,-641.13 -750.48,-716.14 -776.22,-741.88 -1001.98,-741.88 -1100.56,-643.3 -1154.02,-643.3 -1242.38,-731.66 -1242.38,-897.58 -1272.47,-897.58 -1272.47,-732.04 -1348.32,-656.19 -1841.98,-656.19 -1871.6,-626.84
  region: 4470.01,4570.01 4570.01,4570.01 4570.01,4669.75 4470.01,4669.75 4470.01,4570.01
  pour cut-out: 986.4,564.95 986.4,495.14 1005.91,475.63 1064.72,475.63 1087.97,498.88 1087.97,564.58 1074.55,578 997.23,578 986.35,567.12 986.35,564.95 986.4,564.95
  pour cut-out: 978,564.36 978,486.07 995.74,468.33 1067.81,468.33 1089.12,489.64 1089.12,562.29 1069.81,581.6 992.56,581.6 978.11,567.15 978.11,564.36 978,564.36
  region: -619.58,582.39 -619.58,606.01 -635.32,606.01 -635.32,631.6 -578.24,631.6 -578.24,606.01 -595.95,606.01 -595.95,582.39 -619.58,582.39
  region: -306.92,234.01 -306.92,215.81 -300.67,209.56 -210.28,209.56 -189.25,230.59 -132.12,230.59 -107.95,254.76 -107.95,314.08 -24.27,398.46 4.33,398.52 31.91,370.94 256.93,370.94 259.44,373.45 259.44,575.03 256.33,578.14 91.74,578.14 -248.08,238.32 -302.81,238.32 -306.91,234.22 -306.91,234.01 -306.92,234.01
  region: 4420,3220 4520,3220 4520,3320 4420,3320 4420,3220
  region: 161.32,422.52 180.51,422.52 180.51,441.71 240.69,441.71 240.69,377.74 180.51,377.74 180.51,396.93 161.32,396.93 161.32,422.52
  region: -842.52,936.99 -830.52,948.99 -531.65,948.99 -384.82,802.16 -384.82,785.18 -410.41,759.59 -798.15,759.59 -842.71,804.15 -842.71,936.83 -842.52,936.83 -842.52,936.99
  region: 9484.25,4370.08 9584.25,4370.08 9584.25,4470.08 9484.25,4470.08 9484.25,4370.08
  region: -423.42,-36.94 -410.1,-28.85 -300,-28.85 -285,-43.85 -285,-60 -321,-96 -321,-96.06 -360,-135.06 -360,-260.2 -474.8,-375 -711,-375 -738,-402 -738,-585 -681,-642 -681,-791.53 -1018.03,-1098.09 -1018.03,-1137.16 -1042.03,-1161.16 -1150.12,-1161.16 -1192.27,-1119 -1192.27,-1012.18 -945.79,-780 -811.38,-780 -787.38,-756 -787.38,-672 -848.63,-610.75 -849,-324 -753,-228 -453,-228 -429,-204 -429,-47.71 -423.42,-36.94
  region: 5970.47,3220.47 6070.47,3220.47 6070.47,3320.47 5970.47,3320.47 5970.47,3220.47
  pour cut-out: -655.78,2304.42 -655.78,2235.19 -635.09,2214.5 -569.24,2214.5 -543.35,2240.39 -543.35,2307.94 -568.32,2332.91 -640.23,2332.91 -655.83,2317.31 -655.83,2304.42 -655.78,2304.42
  region: -693,288 -702,279 -702,234 -693,225 -504.72,225 -492.72,211.93 -435,211.93 -435,240 -414,240 -414,252 -444,252 -465,273 -468.53,273 -468.53,264 -464.17,264 -443.17,243 -443.17,222 -471,222 -483,234 -483,252.93 -471.88,264 -471.88,273 -543,273 -558,288 -693,288
  pour cut-out: -659.6,2311.61 -659.6,2240.03 -634.65,2215.08 -571.39,2215.08 -541.92,2244.55 -541.92,2312.33 -569.68,2340.09 -640.11,2340.09 -659.68,2320.52 -659.68,2311.61 -659.6,2311.61
  pour cut-out: -1330.16,2306 -1309.26,2326.9 -1257.98,2326.9 -1238.72,2307.64 -1238.72,2243.71 -1250.35,2232.08 -1250.35,1754.14 -1220.16,1723.95 -975.45,1723.95 -712.59,1461.09 -712.59,995.91 -726.12,982.38 -752.66,982.38 -768.65,998.37 -768.65,1433.29 -1003.39,1668.03 -1259.22,1668.03 -1331.01,1739.82 -1331.01,2305.05 -1330.16,2305.9 -1330.16,2306
  pour cut-out: -1879.9,788.2 -1879.9,718.39 -1860.39,698.88 -1801.58,698.88 -1778.33,722.13 -1778.33,787.83 -1791.75,801.25 -1869.07,801.25 -1879.95,790.37 -1879.95,788.2 -1879.9,788.2
  region: 6970,4570 7070,4570 7070,4670 6970,4670 6970,4570
  region: -488.04,791.27 -488.04,802.46 -483.31,807.19 -386.31,807.19 -379.2,800.08 -379.2,790.91 -396,774.11 -471.76,774.11 -488.03,790.38 -488.03,791.27 -488.04,791.27
  region: -311.61,144.96 -311.61,133.15 -145.57,133.15 -77.5,65.07 -8,65 -8,150 -208.5,150 -241.97,144.96 -311.61,144.96
  region: 7935,3420 8035,3420 8035,3520 7935,3520 7935,3420
  region: 119.49,188.27 200.2,188.27 200.2,139.06 336.02,139.06 336.02,42.6 200.2,42.6 200.2,-8.58 174.61,-8.58 174.61,-8.57 145.08,-8.57 145.08,-8.58 119.49,-8.58 119.49,188.27
  pour cut-out: -1890.14,138.74 -1890.14,67.16 -1865.19,42.21 -1801.93,42.21 -1772.46,71.68 -1772.46,139.46 -1800.22,167.22 -1870.65,167.22 -1890.22,147.65 -1890.22,138.74 -1890.14,138.74
  region: -750.62,315.99 -640,315.99 -616.13,292.12 -616.13,226.33 -696.39,146.07 -696.39,88.23 -637.1,28.94 -462.12,28.94 -444.77,46.29 -263.28,46.29 -251.35,58.22 -251.35,89.67 -229.11,111.91 -118.67,111.91 -30.18,23.42 -30.18,-19.57 -56.49,-45.88 -251.94,-45.88 -288.94,-8.88 -513.04,-8.88 -543.93,-25.77 -912.16,-25.77 -967.14,-79.06 -967.14,-123.94 -916.72,-174.36 -796.34,-174.36 -726.41,-244.29 -726.41,-577.24 -648.05,-655.6 -505.33,-655.6 -396.21,-764.72 -396.21,-1104.59 -440.34,-1148.72 -502.63,-1148.72 -537.19,-1114.16 -537.19,-1020.58 -782.46,-775.31 -782.46,-671.59 -852.27,-601.78 -852.27,-400.17 -908.17,-344.27 -908.17,-344.32 -1084.09,-344.32 -1190.79,-237.62 -1190.79,-0.5 -1083.12,107.17 -966.66,107.17 -757.92,315.91 -750.62,315.91 -750.62,315.99
  region: -59.4,646.44 -14.62,646.44 -14.62,550.47 -59.4,550.47 -59.4,579.26 -40.21,579.26 -40.21,617.65 -59.4,617.65 -59.4,646.44
  region: -311.61,123.31 -311.61,107.56 -276.18,107.56 -205,37 -148,37 -148,112 -248.5,111.92 -259.89,123.31 -311.61,123.31
  region: 161.32,537.68 180.51,537.68 180.51,556.87 241.61,556.87 241.61,492.89 180.51,492.89 180.51,512.09 161.32,512.09 161.32,537.68
  region: -641.99,369.04 -609,336 -555.5,336 -555.5,388 -642.03,388 -641.99,369.04
  pour cut-out: -653.97,2308.42 -653.97,2246.62 -628.65,2221.3 -570.66,2221.3 -549.48,2242.6 -549.83,2307.05 -569.13,2326.29 -635.98,2326.42 -653.97,2308.42
  pour cut-out: -1336.64,2312.59 -1336.64,2234.3 -1318.9,2216.56 -1246.83,2216.56 -1225.52,2237.87 -1225.52,2310.52 -1244.83,2329.83 -1322.08,2329.83 -1336.53,2315.38 -1336.53,2312.59 -1336.64,2312.59
  region: -377.8,405.52 -385.77,413.49 -385.77,438.51 -419.01,471.75 -419.01,572.99 -382.11,609.89 -382.11,740.09 -358.53,763.67 -358.53,875.47 -292.46,941.54 -102.44,941.54 -32.06,1011.92 -32.06,2299.45 -6.57,2324.94 128.26,2324.94 151.83,2301.37 151.83,950.39 7.5,806.06 -264.71,806.06 -282.68,788.09 -282.68,648.67 -230.47,596.46 -230.47,516.64 -347.82,399.29 -372.42,399.29 -377.8,405.52
  pour cut-out: -1882.79,783.9 -1882.79,722.1 -1857.47,696.78 -1799.48,696.78 -1778.3,718.08 -1778.65,782.53 -1797.95,801.77 -1864.8,801.9 -1882.79,783.9
  pour cut-out: -1883.7,98.11 -1883.7,134.01 -1865.28,152.43 -1057.46,152.43 -1028.17,177.59 -1002.51,176.83 -973.77,149 -974.13,117.68 -1037.28,59.26 -1865.74,59.26 -1883.23,76.75 -1883.23,98.11 -1883.7,98.11
  region: 5670,4770 5770,4770 5770,4870 5670,4870 5670,4770
  region: 130.61,189.91 198.65,189.91 201.1,187.46 201.1,138.67 597.8,138.67 648.06,188.93 1062.97,188.93 1100.23,151.67 1100.23,59.18 992.48,-48.57 435.94,-48.57 344.36,43.01 200.37,43.01 200.37,-6.84 197.51,-9.7 114.57,-9.7 114.57,190.17 130.61,190.17 130.61,189.91
  pour cut-out: -1338.39,2304.42 -1338.39,2235.19 -1317.7,2214.5 -1251.85,2214.5 -1225.96,2240.39 -1225.96,2307.94 -1250.93,2332.91 -1322.84,2332.91 -1338.44,2317.31 -1338.44,2304.42 -1338.39,2304.42
  region: 1481.27,-1029.15 ccw(c1317.57,-1029.15) 1317.57,-865.45 ccw(c1317.57,-1029.15) 1153.87,-1029.15 ccw(c1317.57,-1029.15) 1317.57,-1192.85 ccw(c1317.57,-1029.15)
  region: -1664.26,2188.03 ccw(c-1827.96,2188.03) -1827.96,2351.73 ccw(c-1827.96,2188.03) -1991.66,2188.03 ccw(c-1827.96,2188.03) -1827.96,2024.33 ccw(c-1827.96,2188.03)
  region: 1479.94,2185.9 ccw(c1316.24,2185.9) 1316.24,2349.6 ccw(c1316.24,2185.9) 1152.54,2185.9 ccw(c1316.24,2185.9) 1316.24,2022.2 ccw(c1316.24,2185.9)
  region: -1667.08,-1023.86 ccw(c-1830.78,-1023.86) -1830.78,-860.16 ccw(c-1830.78,-1023.86) -1994.48,-1023.86 ccw(c-1830.78,-1023.86) -1830.78,-1187.56 ccw(c-1830.78,-1023.86)
  lines w12: -2225,-1420 1775,-1420 1775,2580 -2225,2580 -2225,-1420

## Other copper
Top:
  text "L1" at -203.71,-2431.24 h62.5
Inner Layer 2:
  text "L2" at 26.76,-2437.51 h62.5
Inner Layer 3:
  text "L3" at 294.73,-2433.54 h62.5
Inner Layer 4:
  text "L4" at 550.55,-2430.02 h62.5
Inner Layer 5:
  text "L5" at 778.85,-2444.25 h62.5
Bottom:
  text "L6" at 1043.45,-2433.54 h62.5
Multi-Layer:
  drawing of 13994 lines, arcs and shapes, not listed

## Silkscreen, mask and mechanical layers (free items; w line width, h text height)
Silkscreen Top:
  text "TESTV" at 941.3,2149.78 h25
  text "GND_S" at -1361.31,2101.17 h25
  text "GND_F" at -1201.33,2101.17 h25
  text "DRVH" at -1039.08,2100.04 h25
  text "DRVH" at -888.18,2100.04 h25
  text "VBAT_DCDCCTRL" at -12.71,2098.48 h25
  text "GND_S" at -692.03,2097.48 h25
  text "SW_F" at -218.9,2097.48 h25
  text "GND_F" at -526.38,2096.35 h25
  text "SW_S" at -366.4,2096.35 h25
  text "GND" at 412.5,2093.75 h25
  text "F" at -842.39,2049.73 h25
  text "S" at -992.02,2047.94 h25
  text "F" at 78.05,2039.48 h25
  text "S" at 224.42,2038.34 h25
  text "NRESPWRON2" at 878.8,1987.28 h25
  text "GPOI8" at 1199,1874.55 h19.68 r90
  text "TRAN" at 953.8,1824.78 h25
  text "TPS65911 Eval Board" at -810.94,1798.79 h124.8
  text "GPOI7" at 1199,1762.05 h19.68 r90
  text "PWR002 E3" at -718.31,1686.5 h124.8
  text "EN" at 985.05,1662.28 h25
  text "GPOI6" at 1199,1649.55 h19.68 r90
  text "GPOI5" at 1111.5,1587.05 h19.68
  text "GPOI4" at 1111.5,1487.05 h19.68
  text "DCDC_CTRL" at -806.25,1387.5 h25
  text "GPOI3" at 1111.5,1387.05 h19.68
  text "CLK32KOUT" at -2166.65,1369.86 h25
  text "DCDC1_out" at -1877.18,1369.86 h25
  text "FET_input" at -806.25,1337.5 h25
  text "VBACK" at 678.68,1332.54 h25
  text "GPOI2" at 1111.5,1287.05 h19.68
  text "VRTC" at 405,1275 h25
  text "GPOI1" at 1111.5,1187.05 h19.68
  text "VRTC" at 104.25,1180.75 h25
  text "SW1_F" at -1703.62,1151.29 h25
  text "VBACK" at 537.5,1087.5 h25
  text "PWRHOLD" at 23,1087 h25
  text "GPOI0" at 1111.5,1087.05 h19.68
  text "VFB" at -68.75,1025 h25
  text "SW1_S" at -1696.49,1003.44 h25
  text "GND" at 135.5,987 h25
  text "GND" at -1356.25,975 h25
  text "VDDIO" at 1344.78,924.06 h25
  text "DCDC_CTRL" at -1137.5,906.25 h25
  text "SW" at -267.65,901.07 h29.53
  text "GND" at 706.25,900 h25
  text "GND_F" at -1699.74,860.41 h25
  text "FET_input" at -1137.5,856.25 h25
  text "LDO4" at 87.5,856.25 h25
  text "HDRST" at 1350.38,828.92 h25
  text "FET" at -162.55,806.59 h25
  text "FET" at -646.19,782.13 h25
  text "GND" at 1358.77,728.19 h25
  text "GND_S" at -1692.93,721.99 h25
  text "BOOT1" at 387.5,618.75 h19.68
  text "Xtal" at 0,568.75 h25
  text "GND" at 416.45,512.38 h19.68
  text "GND_S" at 1213.25,506.27 h25
  text "SW2_F" at -1711.8,483.96 h25
  text "LDO3" at 701.84,429.38 h25
  text "SW1" at -637.5,425 h29.53 r90
  text "GND_F" at 1216.05,374.75 h25
  text "AGND_XTAL" at 291.22,371.97 h19.68 r90
  text "A" at -526.82,357.08 h60
  text "SW2_S" at -1710.95,355.41 h25
  text "VCC1" at -620.66,296 h25
  text "VIO_OUT_S" at 1213.25,234.85 h25
  text "VREF" at 199.57,232.71 h25
  text "GND_F" at -1713.43,228.1 h25
  text "VCC2" at -615.23,177.24 h25
  text "VIO_OUT_F" at 1218.85,97.74 h25
  text "GND_S" at -1706.62,89.68 h25
  text "VCCIO" at -216.54,20.87 h25
  text "SW2" at -637.5,-6.25 h29.53 r90
  text "VIO_OUT" at 220.67,-21.48 h25
  text "SWIO" at -102.1,-59.16 h29.53
  text "GND" at -1704.46,-223.21 h25
  text "VBAT_DCDC" at -781.25,-293.75 h25
  text "LDO1" at -101.42,-369.2 h25
  text "LDO2" at -261.56,-371.18 h25
  text "LDO6" at -577.75,-372.91 h25
  text "LDO5" at -960.66,-375.06 h25
  text "LDO8" at -731.25,-375 h25
  text "LDO7" at -427.75,-374.63 h25
  text "VBAT_LDO_S" at -1705.02,-415.63 h25
  text "VBAT_LDO_F" at -1702.75,-551.78 h25
  text "VDDIO" at 729.32,-574.63 h25
  text "VDDIO" at 1025.92,-574.63 h25
  text "VIO_OUT" at 225,-606.25 h25
  text "SWITCH1" at -1652.14,-631.2 h25
  text "VBAT_LDO" at -1400,-631.25 h25
  text "INT1" at -1839.03,-696.57 h25
  text "NRESPWRON" at -2163.01,-699.47 h25
  text "+1.8V" at 609.13,-699.73 h25
  text "VDDIO" at 268.75,-712.5 h25
  text "PWRDN" at -1318.75,-731.25 h25
  text "US130033A" at 1710.43,-735.85 h124.8 r90
  text "+3.3V" at 270.59,-805.75 h25
  text "GND" at -1262.5,-831.25 h25
  text "SYNERGIE-CAD" at 1574.24,-850.07 h124.8 r90
  text "VBAT_ALL_LDO_IN" at -1031.25,-918.75 h25
  text "VDDIO" at -234.92,-1056.71 h25
  text "SLEEP" at -234.92,-1150.46 h25
  text "GND" at -234.92,-1244.21 h25
  text "VBAT_DCDC" at -650,-1308.71 h25
  text "VBAT_VCC3_VCC6" at -1379.39,-1309.77 h25
  text "GND" at -856.5,-1309.85 h25
  text "GND" at -1530.45,-1310.98 h25
  text "S" at -605.67,-1366.27 h25
  text "F" at -466.2,-1367.71 h25
  text "S" at -1263.81,-1368.65 h25
  text "F" at -1124.34,-1370.09 h25
  text "S1" at 2169.72,-2427.76 h62.5
Paste Mask Top:
  text "P1" at 1789.74,-2436.24 h62.5
Solder Mask Top:
  text "M1" at 1284.83,-2431.24 h62.5
Solder Mask Bottom:
  text "M6" at 1522.93,-2431.24 h62.5
Assembly Drawing Top:
  text "A" at -531.65,357.09 h60
  text "TA" at 2561.87,-2426.71 h62.5
Drill Drawing:
  text "FABRICATION CHART" at 6744.2,5550.01 h100
  text "LAYER STACK UP" at -1716.04,5449.65 h50
  text "CU" at -416.04,5449.65 h50
  text "LAYER 1 - TOP SIDE (COMPONENT)" at -2116.04,5299.65 h50
  text "1 oz" at -466.04,5299.65 h50
  text "FINISHED COPPER WEIGHT" at 8668,5235.01 h75
  text "FINISHED" at 4660.76,5225.01 h75
  text "LAYER 2 - GND PLANE" at -2116.04,5199.65 h50
  text "1/2 oz" at -466.04,5199.65 h50
  text "SILKSCREEN" at 5774.35,5125.01 h75
  text "SOLDERMASK" at 7035.07,5125.01 h75
  text "LAYER 3 - SIGNAL" at -2116.04,5099.65 h50
  text "1/2 oz" at -466.04,5099.65 h50
  text "THICKNESS" at 4595.95,5025.01 h75
  text "LAYER 4 - SIGNAL" at -2116.04,4999.65 h50
  text "1/2 oz" at -466.04,4999.65 h50
  text "EXTERNAL" at 8388.27,4975.01 h75
  text "INTERNAL" at 9757.91,4975.01 h75
  text "LAYER 5 - PWR PLANE" at -2116.04,4899.65 h50
  text "1/2 oz" at -466.04,4899.65 h50
  text "LAYER 6 - BOTTOM SIDE (SOLDER)" at -2116.04,4799.65 h50
  text "1 oz" at -466.04,4799.65 h50
  text "0.031" at 4670,4782.51 h62.5
  text "LAYER 1" at 5870,4782.51 h62.5
  text "LAYER 1" at 7170,4782.51 h62.5
  text "1 OZ." at 8420,4782.51 h62.5
  text "1 OZ." at 9685,4782.51 h62.5
  text "LAYER 6" at 5870,4582.51 h62.5
  text "LAYER 6" at 7170,4582.51 h62.5
  text "2 OZ." at 8420,4582.51 h62.5
  text "2 OZ." at 9685,4582.51 h62.5
  text "0.062 (1.6mm)" at 4670,4566.14 h62.5
  text "1/2 OZ." at 10107.65,4401.83 h62.5
  text "0.093" at 4670,4382.51 h62.5
  text "NONE" at 5870,4382.51 h62.5
  text "NONE" at 7170,4382.51 h62.5
  text "OTHER" at 8420,4382.51 h62.5
  text "OTHER" at 9685,4382.51 h62.5
  text "L1 TOP" at -652.24,4378.17 h60
  text "Preg = 0.25mm" at -2077.24,4253.17 h60
  text "L2 GND" at -652.24,4203.17 h60
  text "0.125" at 4670,4182.51 h62.5
  text "Core = 0.4mm" at -2052.24,4128.17 h60
  text "L3 Signal" at -652.24,4053.17 h60
  text "Preg = 0.25mm" at -2077.24,3978.17 h60
  text "L4 Signal" at -652.24,3928.17 h60
  text "DESIGN" at 4648.07,3875.01 h75
  text "TRACE/GAP SPACING" at 6021.19,3869.65 h75
  text "LAYER COUNT" at 8588.65,3870.01 h75
  text "Core = 0.4mm" at -2052.24,3853.17 h60
  text "L5 PWR" at -652.24,3803.17 h60
  text "Preg = 0.25mm" at -2077.24,3728.17 h60
  text "L6 BOT" at -652.24,3653.17 h60
  text "SMD" at 4620,3632.51 h62.5
  text "SINGLE SIDED" at 8135,3632.51 h62.5
  text "2 LAYER" at 9435,3632.51 h62.5
  text "0.010/0.010" at 6170,3628.04 h62.5
  text "THRU-HOLE" at 4620,3432.51 h62.5
  text "6 LAYER" at 8135,3432.51 h62.5
  text "4 LAYER" at 9435,3432.51 h62.5
  text "0.008/0.007" at 6170,3428.04 h62.5
  text "MIX" at 4620,3232.51 h62.5
  text "8 LAYER" at 8135,3232.51 h62.5
  text "10 LAYER" at 9435,3232.51 h62.5
  text "0.006/0.006" at 6170,3228.04 h62.5
  text "OTHER" at 8135,3032.51 h62.5
  text "101.6mm" at -385.23,2915.29 h50
  text "11.6mm" at 1364.07,2754.46 h50
  text "10.0mm" at -2186.61,2751.26 h50
  text "NOTES: UNLESS OTHERWISE SPECIFIED" at 4420,2650.01 h100
  text "1." at 4420,2372.51 h62.5
  text "MATERIAL:" at 4595,2372.51 h62.5
  text "ALL MATERIALS,  INCLUDING BUT NOT LIMITED TO BASE LAMINATE,  BONDING MATERIALS" at 5970,2366.56 h62.5
  text "10.0mm" at 1824.7,2351.41 h50
  text "10.0mm" at -2586.47,2335.41 h50
  text "AND SOLDERMASK COATINGS FORMING THE FINISHED PRINTED CIRCUIT BOARD SHALL MEET" at 5970,2197.51 h62.5
  text "UL-796 REQUIREMENTS AND BE RoHS COMPLIANT AND HAVE A FLAMMABILITY OF UL94V-0." at 5970,2024.53 h62.5
  text "2." at 4420,1852.51 h62.5
  text "BASE LAMINATE:" at 4595,1852.51 h62.5
  text "PLASTIC SHEET, LAMINATED METAL CLAD, ONE OR TWO SIDES, BASE MATERIAL NEMA TYPE FR-4 OR" at 5970,1829.06 h62.5
  text "EQUIVALENT, W/Tg =140 Deg C OR HIGHER. MINIMUM COMPOSITION TEMP (Td) OF 320 Deg c." at 5970,1693.64 h62.5
  text "GLASS EPOXY RESIN, COPPER-CLAD IN ACCORDANCE WITH 6 LAYER STACK-UP," at 5920,1514.06 h62.5
  text "COMPLIANT WITH LEAD FREE PROCESS." at 5920,1395.01 h62.5
  text "3." at 4420,1172.51 h62.5
  text "SOLDERMASK:" at 4595,1172.51 h62.5
  text "SOLDERMASK OVER BARE COPPER (SMOBC) USING LIQUID PHOTO-IMAGEABLE SOLDERMASK IN" at 5970,1156.14 h62.5
  text "ACCORDANCE WITH IPC-SM-840. COLOR: GREEN. MINOR SOLDERMASK ADJUSTMENTS TO FACILITATE" at 5965,1017.51 h62.5
  text "PCB FAB AND OR ASSEMBLY IS ALLOWED PROVIDED NO DEFECTS ARE CREATED TO FINAL ASSEMBLY" at 5965,892.51 h62.5
  text "AS A RESULT." at 5965,767.51 h62.5
  text "4." at 4415,587.51 h62.5
  text "TOLERANCES:" at 4590,587.51 h62.5
  text "UNLESS OTHERWISE SPECIFIED PCB TOLERANCES" at 5970,565.01 h62.5
  text "101.6mm" at -2826.66,542.5 h50
  text "SHALL BE +/- .005 INCHES, HOLE DIAMETERS SHALL BE +/- .003 INCHES." at 5970,434.06 h62.5
  text "5." at 4420,247.51 h62.5
  text "PLATING:" at 4595,247.51 h62.5
  text "HOLES REQUIRING PLATING, SEE HOLE CHART, TO HAVE 1 OZ. (0.0014) MIN. THK MIN." at 5970,231.14 h62.5
  text "THICK COPPER." at 5970,72.51 h62.5
  text "0.1um CHEMICAL GOLD OVER 5um NICKEL." at 5970,-114.99 h62.5
  text "6." at 4420,-127.49 h62.5
  text "FINISH:" at 4595,-127.49 h62.5
  text "7." at 4420,-652.49 h62.5
  text "LEGEND:" at 4595,-652.49 h62.5
  text "IF REQUIRED, SILKSCREEN LEGEND(S) WITH WHITE NON-CONDUCTIVE EPOXY INK." at 5970,-668.86 h62.5
  text "8." at 4420,-902.49 h62.5
  text "MARKINGS:" at 4595,-902.49 h62.5
  text "BOARD MUST BEAR VENDOR'S IDENTIFICATION CODE (ETCH OR WHITE NON-CONDUCTIVE INK)." at 5970,-918.86 h62.5
  text "LOCATION OPTIONAL." at 5970,-1052.49 h62.5
  text "10.0mm" at -2592.86,-1244.06 h50
  text "10.0mm" at 1815.11,-1256.86 h50
  text "9." at 4420,-1272.49 h62.5
  text "WORKMANSHIP:" at 4595,-1277.49 h62.5
  text "BOARD IS TO BE MANUFACTURED PER IPC-A-600 CLASS 2 REQUIREMENTS OR BETTER." at 5970,-1280.47 h62.5
  text "PCB VENDOR IS REQUIRED TO RETURN ANY AND ALL DOCUMENTS SUPPLIED OR ULTIMATELY PURCHASED BY TEXAS" at 5970,-1505.47 h62.5
  text "DOCUMENTATION:" at 4595,-1522.49 h62.5
  text "10." at 4345,-1527.49 h62.5
  text "10.0mm" at -2186.61,-1634.32 h50
  text "11.6mm" at 1373.67,-1653.51 h50
  text "INSTRUMENTS UPON COMPLETION OF PURCHASE ORDER." at 5970,-1702.49 h62.5
  text "11." at 4345,-1927.49 h62.5
  text "DRILL SIZES:" at 4595,-1927.49 h62.5
  text "HOLE DIAMETERS SHOWN ARE FINISHED SIZES AFTER PLATING UNLESS OTHERWISE NOTED." at 5970,-1927.49 h62.5
  text "12." at 4345,-2152.49 h62.5
  text "PANEL BORDER:" at 4595,-2152.49 h62.5
  text "ANY METAL IN BORDER AREA INCLUDING PART NUMBER, DATECODE AND/OR REVISION LETTERS" at 5970,-2158.44 h62.5
  text "MUST BE COVERED WITH SOLDERMASK." at 5970,-2327.49 h62.5
  text "FB" at 2978.87,-2426.71 h62.5
  text "NO DIMENSIONAL, MATERIAL, OR PROCESS CHANGES ARE ALLOWED WITHOUT PRIOR EXPLICIT WRITTEN PERMISSION" at 5970,-2513.44 h62.5
  text "PROCESS CHANGES:" at 4595,-2527.49 h62.5
  text "13." at 4345,-2532.49 h62.5
  text "FROM TEXAS INSTRUMENTS." at 5970,-2707.49 h62.5
  text ".062 +/_ 10%" at 5952.5,-2955.23 h62.5
  text "14." at 4358.62,-2961.58 h62.5
  text "BOARD THICKNESS :" at 4555.47,-2961.58 h62.5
